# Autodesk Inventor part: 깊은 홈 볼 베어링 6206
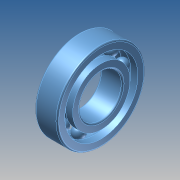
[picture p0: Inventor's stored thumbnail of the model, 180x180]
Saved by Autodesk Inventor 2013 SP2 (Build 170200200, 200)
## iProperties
Created: 2025-06
Part Number: 깊은 홈 볼 베어링 6206
Material: Generic
Document SubType Name: Modeling
Designer: i
Density: 1 g/cm^3
Author: i
변환 표준: STEP AP214IS
전처리기: Build: 200, Release: 2013 SP2 Update 6 - Date: Thu 07/17/2014
전송 단위: 밀리미터
불확실성: 0.01
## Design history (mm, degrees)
node "깊은 홈 볼 베어링 62061"
body "Solid1"
node "Solid1_1"
node "Solid1_2"
node "Solid1_3"
node "Solid1_4"
node "Solid1_5"
node "Solid1_6"
node "Solid1_7"
node "Solid1_8"
node "Solid1_9"
node "Solid1_10"
node "기준1"
node "기준2"
node "기준3"
node "기준4"
node "기준5"
node "기준6"
node "기준7"
node "기준8"
node "기준9"
node "기준10"
node "기준11"
